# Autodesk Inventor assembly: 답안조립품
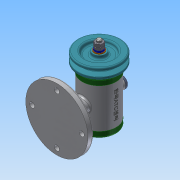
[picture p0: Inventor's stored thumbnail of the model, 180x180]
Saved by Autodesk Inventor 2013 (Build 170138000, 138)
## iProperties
Created: 2018-12
Part Number: 답안조립품
Document SubType Name: Assembly
Designer: Administrator
Author: Administrator
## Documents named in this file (15)
- C:\Users\Administrator\Desktop\481207V1041\답안조립품.iam
- C:\Users\Administrator\Desktop\481207V1041\본체.ipt
- C:\Users\Administrator\Desktop\481207V1041\베어링 15 x 32 x 9.ipt
- C:\Users\Administrator\Desktop\481207V1041\앞커버.ipt
- C:\Users\Administrator\Desktop\481207V1041\뒤커버.ipt
- C:\Users\Administrator\Desktop\481207V1041\축.ipt
- C:\Users\Administrator\Desktop\481207V1041\오일 실 15 25 7.ipt
- C:\Users\Administrator\Desktop\481207V1041\볼트 M4 x 12.ipt
- C:\Users\Administrator\Desktop\481207V1041\키 3 x 3 x 12.ipt
- C:\Users\Administrator\Desktop\481207V1041\V벨트풀리.ipt
- C:\Users\Administrator\Desktop\481207V1041\와셔 8x17.ipt
- C:\Users\Administrator\Desktop\481207V1041\스프링와셔 8.ipt
- C:\Users\Administrator\Desktop\481207V1041\너트 M8.ipt
- 너트 M8.ipt
- C:\Users\Administrator\Desktop\481207V1041\고무캡.ipt
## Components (2 placed, 2 different names)
1. V벨트풀리:1
2. 고무캡:1
